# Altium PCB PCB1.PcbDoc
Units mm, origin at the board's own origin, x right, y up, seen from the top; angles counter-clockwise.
Board outline 67.69 x 56.77 mm, 2 copper layers (Top Layer, Bottom Layer); 103 components, 81 nets, 365 pads, 467 vias.
Unrouted connection lines stored in the file: 20.
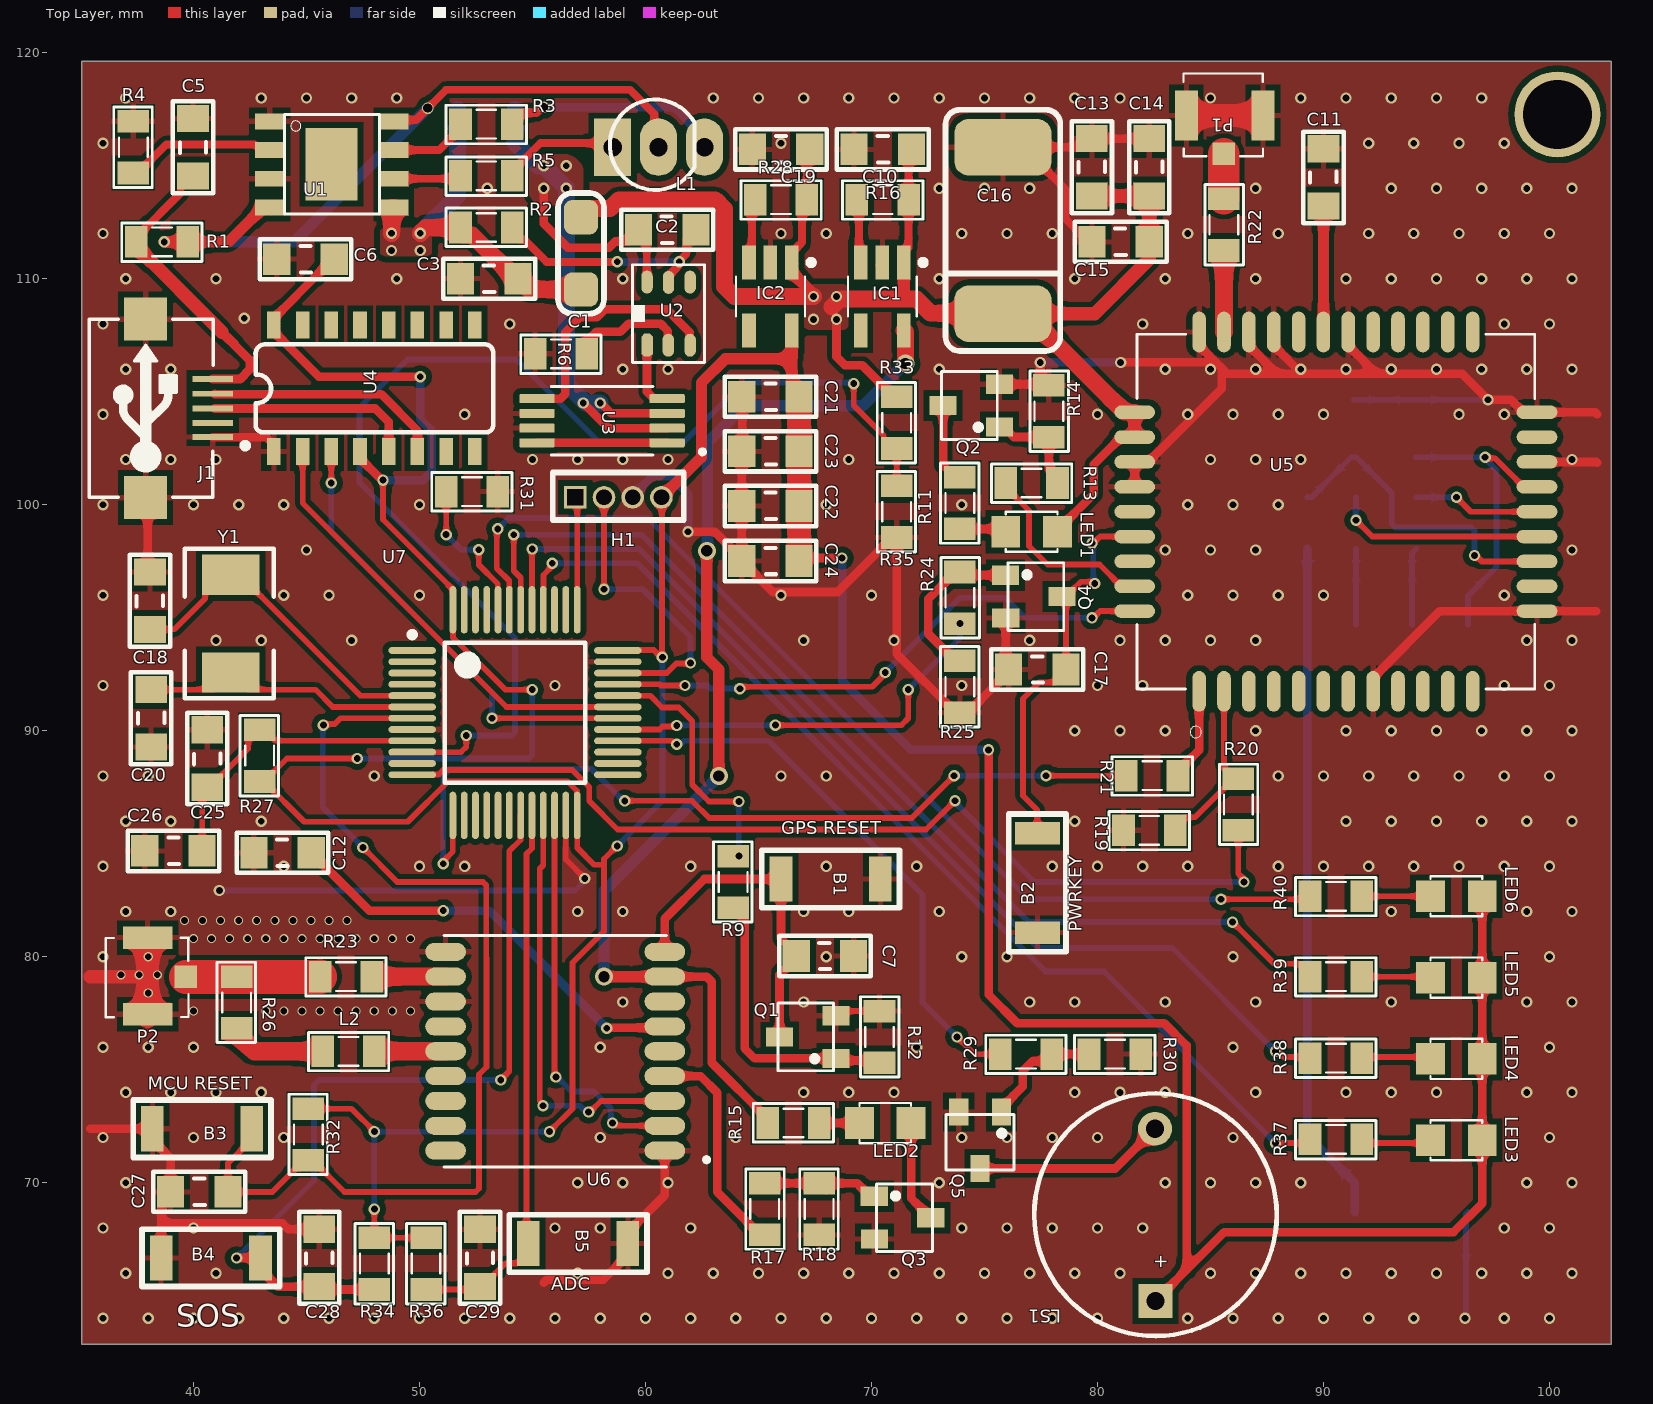
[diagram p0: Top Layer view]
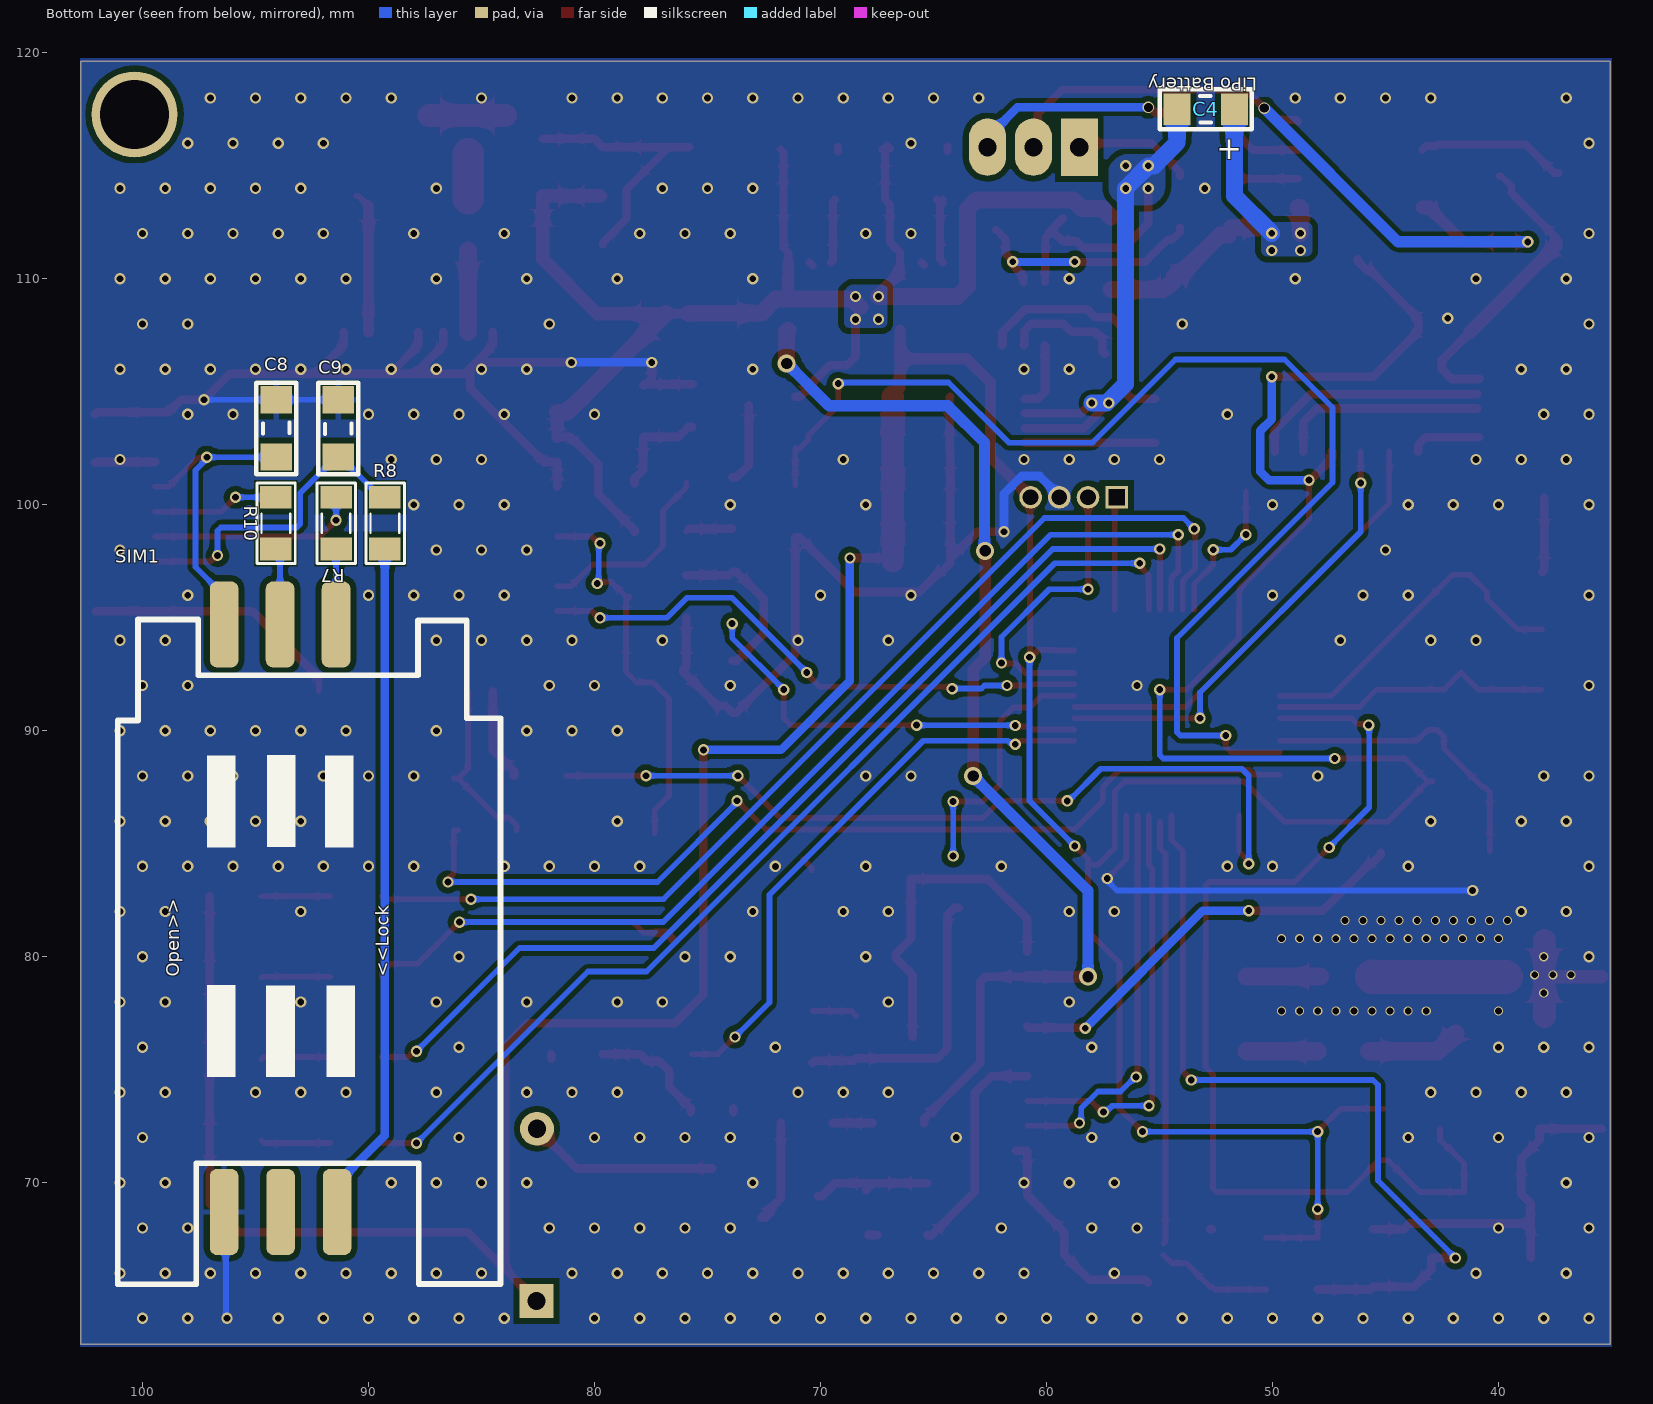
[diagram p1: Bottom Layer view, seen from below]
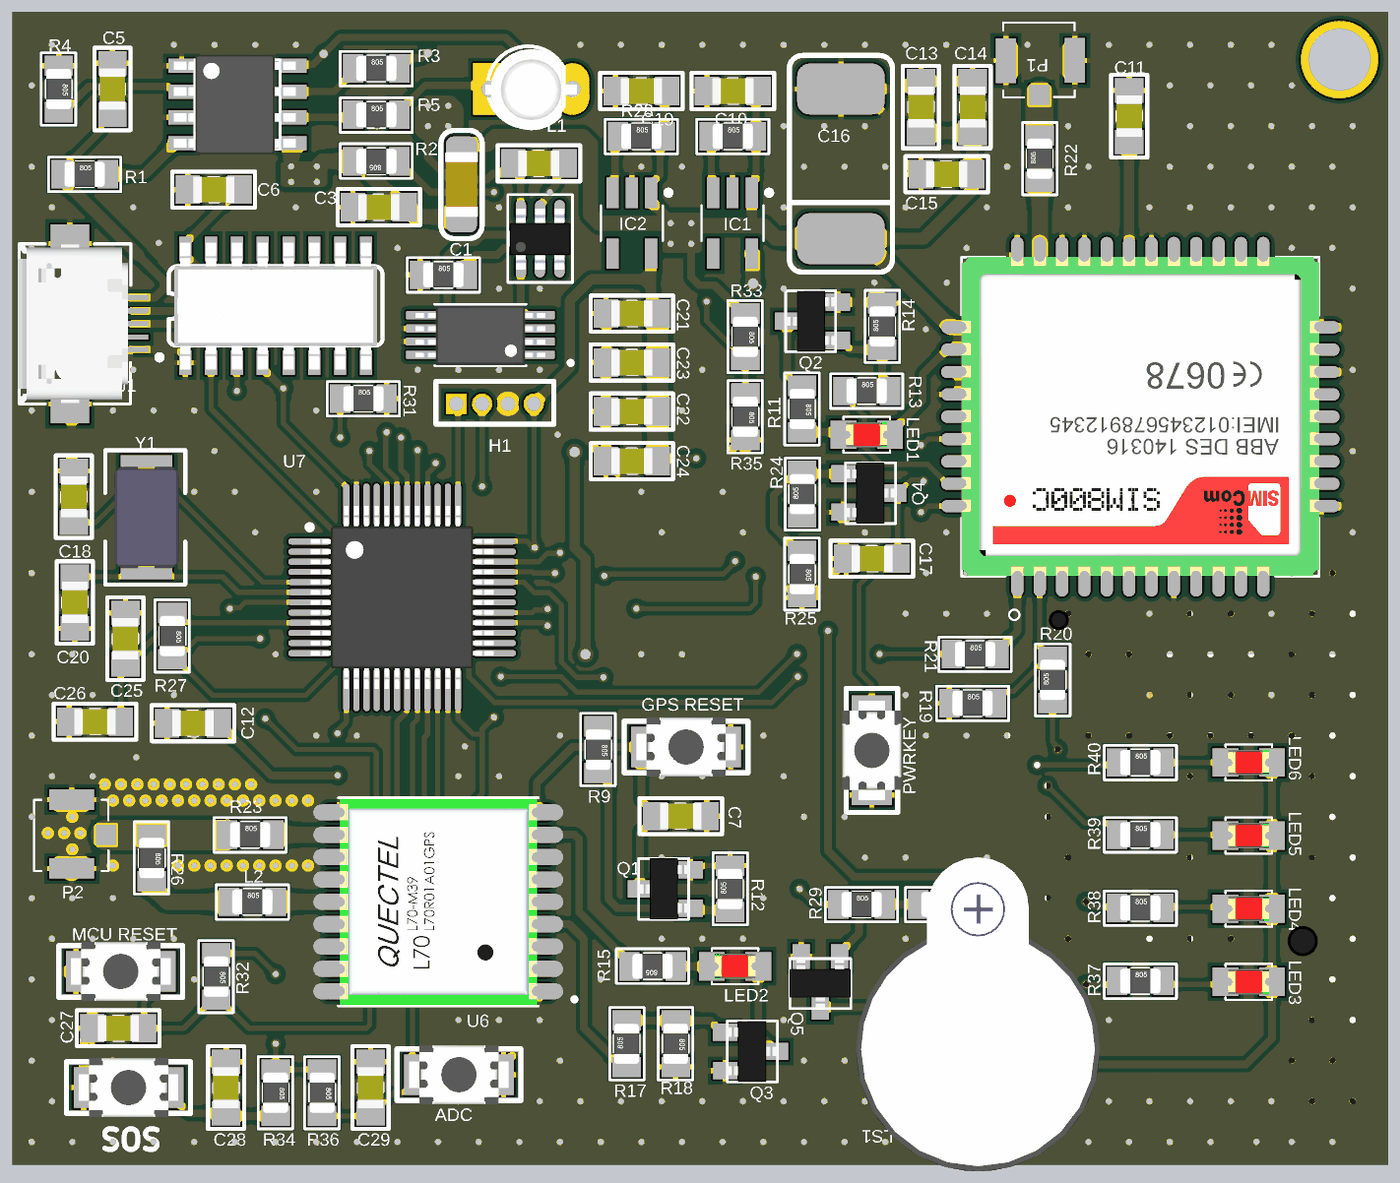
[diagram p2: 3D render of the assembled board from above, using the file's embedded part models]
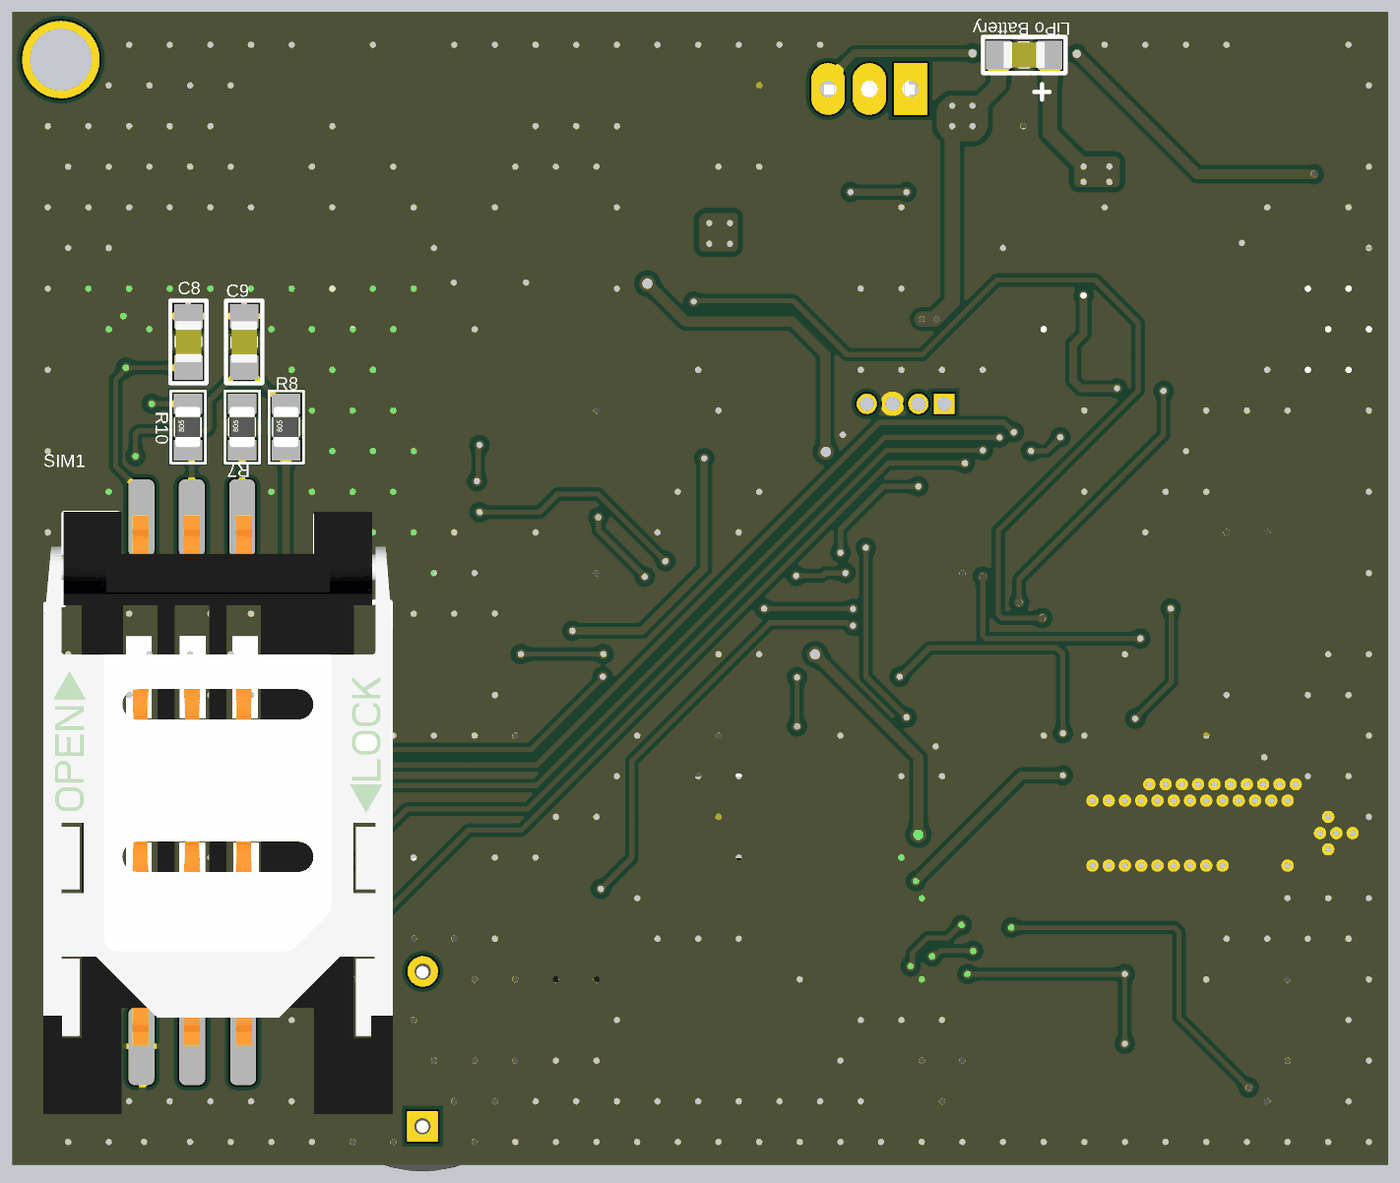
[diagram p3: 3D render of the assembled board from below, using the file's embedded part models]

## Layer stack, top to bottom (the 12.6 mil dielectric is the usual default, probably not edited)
Top Solder: solder mask 0.0102, Solder Resist, Dk 3.5
Top Layer: signal copper 0.0356
Dielectric 1: dielectric 0.32, FR-4, Dk 4.8
Bottom Layer: signal copper 0.0356
Bottom Solder: solder mask 0.0102, Solder Resist, Dk 3.5

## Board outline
35.052,62.865 35.052,119.634 102.743,119.634 102.743,62.865

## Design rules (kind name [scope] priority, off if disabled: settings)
Clearance [All] p1: gap=0.254 ignorepadtopadclearanceinfootprint=TRUE except(0.2: Arc-Arc Arc-Track Arc-SMDPad Arc-THPad Arc-Via Arc-Fill Arc-Poly Arc-Region Arc-Text Arc-Hole Track-Track Track-SMDPad Track-THPad Track-Via Track-Fill Track-Poly Track-Region Track-Text Track-Hole SMDPad-SMDPad)
DiffPairsRouting [All] p1: maxlimit=0.254 minlimit=0.254 mostfreqgap=0.254 toplayer_minwidth=0.381 toplayer_maxwidth=0.381 toplayer_prefwidth=0.381 bottomlayer_minwidth=0.381 bottomlayer_maxwidth=0.381 bottomlayer_prefwidth=0.381 maxuncoupledlength=12.7
HoleSize [All] p1: absolutevalues=TRUE maxlimit=2.54 minlimit=0.5 maxpercent=80.000 minpercent=20.000
MinimumSolderMaskSliver [All] p1: minsoldermaskwidth=0
PlaneConnect [All] p1: planeconnectstyle=Relief reliefexpansion=0.508 reliefentries=4 reliefconductorwidth=0.508 reliefairgap=0.254
PolygonConnect [All] p1: thpad.connectstyle=Direct thpad.reliefconductorwidth=0.508 thpad.reliefentries=4 thpad.polygonreliefangle="90 Angle" thpad.airgapwidth=0.254 smdpad.connectstyle=Relief smdpad.reliefconductorwidth=0.254 smdpad.reliefentries=4 smdpad.polygonreliefangle="90 Angle" smdpad.airgapwidth=0.254 via.connectstyle=Direct via.reliefconductorwidth=0.254 via.reliefentries=4 via.polygonreliefangle="90 Angle" via.airgapwidth=0.254
RoutingVias [All] p1: holewidth=0.3 width=0.5 viastyle="Through Hole" minholewidth=0.1 minwidth=0.1 maxholewidth=0.75 maxwidth=1
SilkToSilkClearance [All] p1: silktosilkclearance=0
SilkToSolderMaskClearance SilkscreenOverComponentPads [IsPad] p1: minsilkscreentomaskgap=0 clearancetoexposedcopper=TRUE
SolderMaskExpansion [All] p1: expansion=0.102
UnRoutedNet [All] p1: checkbadconnections=TRUE
Width [All] p1: maxlimit=3 minlimit=0.127 preferedwidth=0.2
23 further rules are at their usual default settings.

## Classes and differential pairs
component class Designator: B3 B4 B5 C18 C19 C20 C21 C22 C23 C24 C25 C26 C27 C28 C29 H1 IC2 LED3 LED4 LED5 LED6 LS1 Q5 R27 R28 R29 R30 R31 R32 R33 R34 R35 R36 R37 R38 R39 R40 U7 Y1
differential pair D: +D_P -D_N

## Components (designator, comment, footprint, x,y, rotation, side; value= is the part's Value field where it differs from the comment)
B1 "Button 3x4x2.5" "Button 3x4x2.5" 68.199,83.439 r180 top
B2 "Button 3x4x2.5" "Button 3x4x2.5" 77.343,83.271 r90 top
B3 "Button 3x4x2.5" "Button 3x4x2.5" 40.386,72.39 r0 top
B4 "Button 3x4x2.5" "Button 3x4x2.5" 40.767,66.675 r0 top
B5 "Button 3x4x2.5" "Button 3x4x2.5" 57.023,67.31 r180 top
C1 "Pad Switch ON/OFF" CAP_3216 57.15,111.125 r90 top value=33p
C2 "100nF" CAP_0805 60.96,112.141 r180 top value=33p
C3 "10uF" CAP_0805 53.086,109.982 r180 top value=33p
C4 "LiPo Battery" CAP_0805 52.959,117.475 r0 bottom value=33p
C5 "100nF" CAP_0805 40.005,115.824 r270 top value=33p
C6 "100nF" CAP_0805 44.958,110.896 r0 top value=33p
C7 "100nF" CAP_0805 67.945,80.01 r180 top value=33p
C8 "100nF" CAP_0805 94.107,103.378 r90 bottom value=33p
C9 "22pF" CAP_0805 91.313,103.378 r270 bottom value=33p
C10 "1uF" CAP_0805 70.5,115.75 r0 top value=33p
C11 "10nF" CAP_0805 89.976,114.485 r90 top value=33p
C12 "10nF" CAP_0805 43.942,84.582 r180 top value=33p
C13 "1uF" CAP_0805 79.731,114.935 r90 top value=33p
C14 "33pF" CAP_0805 82.271,114.935 r90 top value=33p
C15 "10pF" CAP_0805 81.026,111.608 r180 top value=33p
C16 "100uF" CAP_7343 75.819,112.268 r90 top
C17 "100nF" CAP_0805 77.343,92.735 r0 top value=33p
C18 "22pF" CAP_0805 38.1,95.758 r270 top value=33p
C19 "1uF" CAP_0805 66,115.75 r0 top value=33p
C20 "22pF" CAP_0805 38.1,90.551 r90 top value=33p
C21 "100nF" CAP_0805 65.532,104.8 r0 top value=33p
C22 "100nF" CAP_0805 65.532,99.974 r0 top value=33p
C23 "100nF" CAP_0805 65.532,102.387 r0 top value=33p
C24 "4.7uF" CAP_0805 65.532,97.536 r0 top value=33p
C25 "1uF" CAP_0805 40.64,88.773 r270 top value=33p
C26 "10nF" CAP_0805 39.116,84.709 r0 top value=33p
C27 "100nF" CAP_0805 40.259,69.621 r0 top value=33p
C28 "100nF" CAP_0805 45.593,66.675 r270 top value=33p
C29 "100nF" CAP_0805 52.705,66.675 r270 top value=33p
H1 "Header 1.27mm" "Header 1.27mm" 56.896,100.33 r0 top
IC1 "RT9013" SOT23-5 70.485,109.22 r270 top
IC2 "RT9013" SOT23-5 65.532,109.22 r270 top
J1 "USB-5" USB-M1 40.855,104.264 r90 top
L1 "LED 3mm" "LED-3MM 2 MAU" 60.579,115.824 r0 top
L2 "47nH" RES-SMD-0805 46.863,75.819 r0 top
LED1 "LED" LED-0805-Red 78.232,98.806 r180 top value="LED 3 ly Single Colour"
LED2 "LED" LED-0805-Red 69.469,72.644 r0 top value="LED 3 ly Single Colour"
LED3 "LED RED" LED-0805-Red 97.028,71.882 r180 top value="LED 3 ly Single Colour"
LED4 "LED YELLOW" LED-0805-Red 97.028,75.48 r180 top value="LED 3 ly Single Colour"
LED5 "LED GREEN" LED-0805-Red 97.028,79.079 r180 top value="LED 3 ly Single Colour"
LED6 "LED RED" LED-0805-Red 97.028,82.677 r180 top value="LED 3 ly Single Colour"
LS1 "Speaker" SPEAKER 82.563,64.77 r90 top
P1 "Antenna" IPXS 85.598,115.951 r270 top
P2 "Antenna" IPXS 39.25,79.119 r0 top
Q1 "C1815" SOT23D 67.183,76.454 r90 top
Q2 "C1815" SOT23D 74.422,104.394 r90 top
Q3 "C1815" SOT23D 71.374,68.453 r270 top
Q4 "C1815" SOT23D 77.191,95.936 r270 top
Q5 "C1815" SOT23D 74.803,71.882 r180 top
R1 "0.4R" RES-SMD-0805 38.608,111.633 r0 top
R2 "100R" RES-SMD-0805 52.959,112.268 r180 top
R3 "1k" RES-SMD-0805 52.959,116.84 r0 top
R4 "1.2k" RES-SMD-0805 37.338,115.824 r270 top
R5 "1k" RES-SMD-0805 52.959,114.554 r0 top
R6 "1k" RES-SMD-0805 56.261,106.68 r0 top
R7 "51R" RES-SMD-0805 91.44,99.187 r90 bottom
R8 "51R" RES-SMD-0805 89.281,99.187 r90 bottom
R9 "4.7k" RES-SMD-0805 63.881,83.312 r270 top
R10 "51R" RES-SMD-0805 94.107,99.187 r90 bottom
R11 "1k" RES-SMD-0805 73.914,100.076 r270 top
R12 "47k" RES-SMD-0805 70.358,76.454 r90 top
R13 "4.7k" RES-SMD-0805 77.089,100.965 r0 top
R14 "47k" RES-SMD-0805 77.851,104.14 r90 top
R15 "1k" RES-SMD-0805 66.548,72.644 r180 top
R16 "10k" RES-SMD-0805 70.5,113.5 r0 top
R17 "4.7k" RES-SMD-0805 65.278,68.834 r90 top
R18 "47k" RES-SMD-0805 67.691,68.834 r270 top
R19 "5.6k" RES-SMD-0805 82.296,85.598 r0 top
R20 "1k" RES-SMD-0805 86.233,86.741 r90 top
R21 "1k" RES-SMD-0805 82.423,88.011 r0 top
R22 "0R" RES-SMD-0805 85.598,112.395 r90 top
R23 "0R" RES-SMD-0805 46.75,79.121 r0 top
R24 "4.7k" RES-SMD-0805 73.914,95.885 r90 top
R25 "47k" RES-SMD-0805 73.914,91.948 r270 top
R26 "10R" RES-SMD-0805 41.91,77.978 r270 top
R27 "0R" RES-SMD-0805 42.926,88.9 r270 top
R28 "10k" RES-SMD-0805 66,113.5 r0 top
R29 "4.7k" RES-SMD-0805 76.835,75.692 r0 top
R30 "47k" RES-SMD-0805 80.772,75.692 r0 top
R31 "100k" RES-SMD-0805 52.324,100.584 r0 top
R32 "10k" RES-SMD-0805 45.085,72.136 r270 top
R33 "10k" RES-SMD-0805 71.12,103.632 r270 top
R34 "10k" RES-SMD-0805 48.006,66.421 r270 top
R35 "22k" RES-SMD-0805 71.12,99.695 r270 top
R36 "10k" RES-SMD-0805 50.292,66.421 r270 top
R37 "1k" RES-SMD-0805 90.551,71.92 r0 top
R38 "1k" RES-SMD-0805 90.551,75.518 r0 top
R39 "1k" RES-SMD-0805 90.551,79.121 r0 top
R40 "1k" RES-SMD-0805 90.551,82.677 r0 top
SIM1 "SIM SOCKET 6P" "SIM SOCKET 6P" 104.521,67.056 r90 bottom
U1 "TP4056" TP4056 46.126,115.062 r0 top
U2 "DW01A" SOT23-6 60.894,108.57 r90 top
U3 "FS8205A" FS8205A 58.08,103.774 r180 top
U4 "CH340C" SO016 48.006,105.156 r0 top
U5 "SIM800C" LCC110P1570X1760X250-42N 90.551,99.695 r90 top
U6 "L70-RL" XCVR_L70-RL 56.007,75.819 r180 top
U7 "STM32" "LQFP 48" 54.229,90.805 r0 top
Y1 "8Mhz" "Thach Anh 2 chan SMD5032" 41.656,94.742 r90 top value=4Mhz

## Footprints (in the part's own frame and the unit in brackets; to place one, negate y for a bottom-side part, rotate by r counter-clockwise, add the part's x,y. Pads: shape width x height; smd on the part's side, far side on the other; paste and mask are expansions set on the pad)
"Button 3x4x2.5" [mm]
  rect 1x2 smd: 15(-2.2,0) 19(2.2,0)
  silkscreen extent -3.05,-1.27 3.05,1.27, body extent -2.45,-1.45 2.45,1.45, height 2
CAP_0805 [mm]
  rect 1.2x1.4 smd: 1(-1.27,-0.025) 2(1.27,-0.025)
  silkscreen extent -2.03,-0.91 2.03,0.86, body extent -1.01,-0.66 1.01,0.61, height 0.61
CAP_3216 [mil]
  rrect50% 60x60 smd: 1(-62.99,0) s(62.99,0)
  silkscreen extent -105,-40 105,40, body extent -63,-31 63,31, height 39
CAP_7343 [mm] "Capacitor Tantalum 7343"
  rrect50% 2.5x4.3 smd: 1(-3.81,0) 2(3.556,0)
  silkscreen extent -5.46,-2.54 5.21,2.54, body extent -3.81,-2.29 3.56,2.29, height 3
FS8205A [mm]
  rrect25% 1.56x0.4 smd: 1(-2.88,1.031) 2(-2.88,0.381) 3(-2.88,-0.269) 4(-2.88,-0.919) 5(2.88,-0.919) 6(2.88,-0.269) 7(2.88,0.381) 8(2.88,1.031)
  silkscreen extent -4.54,-1.46 2.25,1.57, body extent -3.2,-1.4 3.2,1.53, height 1.2
"Header 1.27mm" [mm]
  rect 1x1 hole 0.7 square: 1(0,0)
  round 1 hole 0.7: 2(1.27,0) 3(2.54,0) 4(3.81,0)
  silkscreen extent -1,-1 4.8,1.1
IPXS [mm] "SOT 23 _ 1-3-2"
  rect 1x1 smd: 1(0.415,-0.01)
  rect 2.2x1 smd: 2(-1.273,-1.658) 3(-1.278,1.73)
  silkscreen extent -3.13,-1.79 0.53,1.73, body extent -2.83,-1.49 0.31,1.56, height 1.55
LCC110P1570X1760X250-42N [mm]
  oval 1.8x0.6 smd: 1(-7.95,6.05) 2(-7.95,4.95) 3(-7.95,3.85) 4(-7.95,2.75) 5(-7.95,1.65) 6(-7.95,0.55) 7(-7.95,-0.55) 8(-7.95,-1.65) 9(-7.95,-2.75) 10(-7.95,-3.85) 11(-7.95,-4.95) 12(-7.95,-6.05) 22(7.95,-6.05) 23(7.95,-4.95) 24(7.95,-3.85) 25(7.95,-2.75) 26(7.95,-1.65) 27(7.95,-0.55) 28(7.95,0.55) 29(7.95,1.65) 30(7.95,2.75) 31(7.95,3.85) 32(7.95,4.95) 33(7.95,6.05)
  oval 0.6x1.8 smd: 13(-4.4,-8.9) 14(-3.3,-8.9) 15(-2.2,-8.9) 16(-1.1,-8.9) 17(0,-8.9) 18(1.1,-8.9) 19(2.2,-8.9) 20(3.3,-8.9) 21(4.4,-8.9) 34(4.4,8.9) 35(3.3,8.9) 36(2.2,8.9) 37(1.1,8.9) 38(0,8.9) 39(-1.1,8.9) 40(-2.2,8.9) 41(-3.3,8.9) 42(-4.4,8.9)
  silkscreen extent -10,-8.8 7.85,8.8, body extent -7.83,-8.8 7.87,8.8, height 2.31
"LED-3MM 2 MAU" [mil] "LED 3 PIN, 3ly Two colour"
  rect 65x100 hole 32: 1(-80,0)
  oval 65x100 hole 32: 2(0,0) 3(80,0)
  silkscreen extent -85,-75 63,83, body extent -89,-80 89,77, height 293
LED-0805-Red [mil]
  rect 50x55 smd: 1(0,0) 2(90,0)
  silkscreen extent 0,-35 90,35, body extent 5,-25 85,25, height 43
"LQFP 48" [mm] "LQFP, 48-Leads, Body 7,00x7,00mm, Pitch 0,50mm, IPC Medium Density"
  oval 2.1x0.3 smd: 1(-4.55,2.75) 2(-4.55,2.25) 3(-4.55,1.75) 4(-4.55,1.25) 5(-4.55,0.75) 6(-4.55,0.25) 7(-4.55,-0.25) 8(-4.55,-0.75) 9(-4.55,-1.25) 10(-4.55,-1.75) 11(-4.55,-2.25) 12(-4.55,-2.75) 25(4.55,-2.75) 26(4.55,-2.25) 27(4.55,-1.75) 28(4.55,-1.25) 29(4.55,-0.75) 30(4.55,-0.25) 31(4.55,0.25) 32(4.55,0.75) 33(4.55,1.25) 34(4.55,1.75) 35(4.55,2.25) 36(4.55,2.75)
  oval 0.3x2.1 smd: 13(-2.75,-4.55) 14(-2.25,-4.55) 15(-1.75,-4.55) 16(-1.25,-4.55) 17(-0.75,-4.55) 18(-0.25,-4.55) 19(0.25,-4.55) 20(0.75,-4.55) 21(1.25,-4.55) 22(1.75,-4.55) 23(2.25,-4.55) 24(2.75,-4.55) 37(2.75,4.55) 38(2.25,4.55) 39(1.75,4.55) 40(1.25,4.55) 41(0.75,4.55) 42(0.25,4.55) 43(-0.25,4.55) 44(-0.75,4.55) 45(-1.25,4.55) 46(-1.75,4.55) 47(-2.25,4.55) 48(-2.75,4.55)
  silkscreen extent -4.67,-3.1 3.1,3.57, body extent -4.5,-4.5 4.5,4.5, height 1.6
RES-SMD-0805 [mil]
  rect 39.37x55 smd: 1(-45,0) 2(45,0)
  silkscreen extent -70,-34 70,33, body extent -39,-25 39,25, height 31
"SIM SOCKET 6P" [mil]
  rrect50% 150x50 smd: 1(65,-320) 2(1088.62,-320) 3(65,-418.43) 4(1088.62,-417.5) 5(65,-516.85) 6(1088.62,-515)
  silkscreen extent -61,-802 1097,-135, body extent -66,-807 1101,-130, height 103
SO016 [mm]
  rect 0.6x1.2 smd: 1(-4.445,-2.8) 2(-3.175,-2.8) 3(-1.905,-2.8) 4(-0.635,-2.8) 5(0.635,-2.8) 6(1.905,-2.8) 7(3.175,-2.8) 8(4.445,-2.8) 9(4.445,2.8) 10(3.175,2.8) 11(1.905,2.8) 12(0.635,2.8) 13(-0.635,2.8) 14(-1.905,2.8) 15(-3.175,2.8) 16(-4.445,2.8)
  silkscreen extent -5.84,-2.67 5.26,1.95, body extent -4.99,-3.13 4.99,3.1, height 1.58
SOT23-5 [mm] "SOT23, 5-Leads, Body 3.0x3.0mm (max), Pitch 0.95mm, IPC Medium Density"
  rect 1.5x0.6 smd: 1(-1.5,0.95) 2(-1.5,0) 3(-1.5,-0.95) 4(1.5,-0.95) 5(1.5,0.95)
  silkscreen extent -1.62,-1.52 0.87,1.93, body extent -1.75,-1.52 1.75,1.53, height 1.45
SOT23-6 [mil]
  oct 40x20 smd: 1(-59.41,32.4)
  oval 40x20 smd: 2(-59.41,-4.6) 3(-59.41,-42.6) 4(50.59,-42.6) 5(50,-5) 6(50.59,32.4)
  silkscreen extent -89,-68 81,57, body extent -64,-64 54,54, height 51
SOT23D [mm] "SOT 23C - 1-3-2 - BCE"
  rect 0.85x1.2 smd: 1(-0.95,-1.25) 2(0.94,-1.245) 3(0,1.25)
  silkscreen extent -1.5,-1.14 1.5,1.32, body extent -1.5,-1.17 1.5,1.33, height 1.06
SPEAKER [mm]
  rect 1.5x1.5 hole 0.8: 1(0,0)
  round 1.5 hole 0.8: 2(7.62,0.013)
  silkscreen extent -1.55,-5.38 9.18,5.36, body extent -2.22,-6 13.24,6, height 4.5
"Thach Anh 2 chan SMD5032" [mil] "DO-214-AA/SMB; 2 C-Bend Leads; Body 5.3 x 3.6 mm, inc. leads (LxW)"
  rect 70x100 smd: 1(-85,0) 2(85,0)
  silkscreen extent -130,-75 130,80, body extent -98,-63 98,63, height 51
TP4056 [mm]
  rect 1.3x0.7 smd: 1(-2.75,1.905) 2(-2.75,0.635) 3(-2.75,-0.635) 4(-2.75,-1.905) 5(2.75,-1.905) 6(2.75,-0.635) 7(2.75,0.635) 8(2.75,1.905)
  rect 2.3x3.2 smd: GND(-0.025,0)
  silkscreen extent -2.1,-2.2 2.1,2.2, body extent -3.13,-2.45 2.87,2.45, height 1.75
USB-M1 [mil]
  rect 10x70 smd: 1(51.18,0) 2(25.59,0) 3(0,0) 4(-25.59,0) 5(-50,0)
  rect 74.8x74.8 smd: 5(-155.51,116.84) 5(155.51,116.84)
  silkscreen extent -155,-1 155,215, body extent -157,5 158,218, height 107
XCVR_L70-RL [mm]
  oval 1.8x0.8 smd paste-2: 1(-4.85,4.4) 2(-4.85,3.3) 3(-4.85,2.2) 4(-4.85,1.1) 5(-4.85,0) 6(-4.85,-1.1) 7(-4.85,-2.2) 8(-4.85,-3.3) 9(-4.85,-4.4) 10(4.85,-4.4) 11(4.85,-3.3) 12(4.85,-2.2) 13(4.85,-1.1) 14(4.85,0) 15(4.85,1.1) 16(4.85,2.2) 17(4.85,3.3) 18(4.85,4.4)
  silkscreen extent -6.8,-5.13 4.92,5.13, body extent -4.85,-5.05 4.85,5.05, height 2.52

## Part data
C1 C2 C3 C4 C5 C6 C7 C8 C9 C10 C11 C12 C13 C14 C15 C17 C18 C19 C20 C21 C22 C23 C24 C25 C26 C27 C28 C29: library part CapSMD, "Capacitor"
C16: library part CAP_TAN_SMD, "Polazied Tantalum Capacitor"
IC1 IC2: "RT9013-33GB IC REG LINEAR 3.3V 500mA SOT23-5"
J1: Manufacturer=FCI, Manufacturer Part Number=10118193-0001LF, Supplier Part Number 1=609-4616-1-ND
L1: library part "LED 3m 2 mau Anot chung", "C?m"
L2 R1 R2 R3 R4 R5 R6 R7 R8 R9 R10 R11 R12 R13 R14 R15 R16 R17 R18 R19 R20 R21 R22 R23 R24 R25 R26 R27 R28 R29 R30 R31 R32 R33 R34 R35 R36 R37 R38 R39 R40: library part "Resistor - SMD", "Resistor", Manufacturer="Generic Components"
LED1 LED2: "LED Single colour Green and Red"
LED3 LED4 LED5 LED6: library part LED, "LED Single colour Green and Red"
LS1: "Còi chíp 3V"
P1 P2: library part IPXSx66, "Antenna GSM GPS"
Q1 Q2 Q3 Q4 Q5: library part 2SC1815, "NPN 600mW, ECB"
U1: "Complete single cell Li-Ion battery with a constant current / constant voltage linear charger"
U2: "One Cell Lithium-ion/Polymer Battery Protection IC"
U4: "USB to serial chip CH340", Package=Package
U5: "Module: GSM/Bluetooth; GPRS; 2G; 1800MHz, 900MHz; 85.6kbps; SMD", Package=None
U6: "L70-RL, a low cost ROM-based GPS module, brings the high performance of MTK positioning engine to industrial applications with its compact profile, ultra low power consumption and fast positioning capability", Package=None
U7: library part STM32F103C8T6, "STM32 ARM-based 32-bit MCU with 64 Kbytes Flash, 64-pin LQFP, Industrial Temperature"
Y1: library part "Thach Anh 2 chan SMD 5032", "Crystal For all Crystal 2pin."

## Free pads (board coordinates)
  round 3.81 hole 3.048: 0(100.355,117.272)

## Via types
v1: diameter 0.5, hole 0.3, Top Layer to Bottom Layer, tented both sides, 423 vias
v2: diameter 0.4, hole 0.3, Top Layer to Bottom Layer, 38 vias
v3: diameter 0.8, hole 0.5, Top Layer to Bottom Layer, tented both sides, 4 vias
v4: diameter 0.5, hole 0.4, Top Layer to Bottom Layer, tented both sides, 2 vias

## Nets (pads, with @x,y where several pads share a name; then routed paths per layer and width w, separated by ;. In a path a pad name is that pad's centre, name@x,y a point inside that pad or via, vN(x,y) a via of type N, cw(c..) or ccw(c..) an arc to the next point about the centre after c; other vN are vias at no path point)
3V3: C6.2 C21.2 C22.2 C23.2 C24.2 H1.4 IC2.5 LED3.1 LED4.1 LED5.1 LED6.1 LS1.1 R27.2 R32.1 R34.1 R36.1 U4.4 U4.16 U7.24 U7.36 U7.48 | length 214.1
  Top Layer w0.254: R27.2 R27.2@43.124,87.757 ; R32.1 46.99,73.279 v1(48.006,72.263) ; v1(47.244,88.773) 44.14,88.773 R27.2@43.124,87.757 ; v1(48.006,68.834) R34.1 R36.1 ; v1(48.387,101.092) 48.387,99.347 51.479,96.255 U7.48 51.488,95.346 51.488,94.13 53.796,91.821 v1(54.991,91.821) ; v1(55.753,72.263) 56.769,73.279 56.769,79.733 58.166,81.13 58.166,84.328 58.736,84.898 v1(58.749,84.898) ; 58.122,84.074 57.726,84.074 56.979,84.821 U7.24 56.97,86.264 56.97,87.338 56.552,87.757 51.257,87.757 49.479,85.979 44.903,85.979 R27.2@43.124,87.757 ; U7.36 59.68,93.555 59.694,93.57 60.364,93.57 60.683,93.25 v1(60.75,93.25) 60.728,93.272 60.728,100.308 H1.4
  Top Layer w0.381: C6.2 46.228,110.771 45.818,110.361 45.666,110.361 43.561,108.256 U4.16 43.561,107.656 45.553,105.664 v1(50.038,105.664) ; U4.4 47.371,102.056 48.311,101.116 48.363,101.116 v1(48.387,101.092) ; C24.2 66.936,97.644 v1(68.7,97.644) ; v1(75.184,89.154) 75.184,78.328 76.453,77.059 82.961,77.059 83.947,76.073 83.947,66.154 ; LS1.1 83.947,66.154 ; LED6.1 LED5.1 LED4.1 LED3.1 97.028,69.088 95.758,67.818 85.611,67.818 83.947,66.154
  Top Layer w0.5: H1.4 62.484,102.108 62.484,105.41 63.532,106.458 66.482,106.458 ; IC2.5 66.482,106.458 ; C21.2@66.802,104.875 66.482,105.195 66.482,106.458
  Top Layer w0.75: C21.2 C21.2@66.802,104.875
  Top Layer w1: C24.2 C22.2 C23.2 C21.2
  Bottom Layer w0.254: v1(47.244,88.773) 54.842,88.773 54.991,88.922 v1(54.991,91.821) ; v1(48.006,68.834) v1(48.006,72.263) v1(55.753,72.263) ; v1(58.749,84.898) 60.75,86.9 v1(60.75,93.25)
  Bottom Layer w0.381: v1(48.387,101.092) 50.165,101.092 50.546,101.473 50.546,103.271 50.038,103.779 v1(50.038,105.664) ; v1(68.7,97.644) 68.707,97.637 68.707,92.202 71.755,89.154 v1(75.184,89.154)
3V3GPS: IC1.5 R15.2 U6.8 | length 49.8
  Top Layer w0.381: U6.8 62.713,79.119 62.937,78.896 62.937,75.311 65.405,72.842 R15.2
  Top Layer w0.5: v3@58.168,79.119 U6.8 ; v3(62.717,97.961) 62.717,93.247 63.25,92.714 v3(63.25,88)
  Top Layer w0.75: v3(58.166,79.121) v3@58.168,79.119 ; IC1.5 71.5,107.655 v3(71.5,106.25)
  Bottom Layer w0.5: v3(58.166,79.121) 58.166,82.916 v3(63.25,88) ; v3(62.717,97.961) 62.75,97.995 62.75,102.755 64.378,104.383 69.621,104.383 71.488,106.25 v3(71.5,106.25)
+5: C5.2 J1.1 R1.1 | length 13.6
  Top Layer w0.3: R1.1 R1.1@37.465,111.831 ; 39.43,113.796 39.43,114.104 39.88,114.554 C5.2
  Top Layer w0.35: R1.1@37.465,111.831 39.43,113.796
  Top Layer w0.4: J1.1 42.064,105.564 42.5,106 42.5,106.399 41.254,107.645
  Top Layer w0.6: R1.1 37.465,111.435 41.254,107.645
BOOT0: R31.1 U7.44 | length 6.6
  Top Layer w0.254: v1(51.181,98.679) R31.1 ; v1(52.621,98.009) 52.621,97.347 53.47,96.498 53.47,95.364 U7.44
  Bottom Layer w0.254: v1(51.181,98.679) 51.851,98.009 v1(52.621,98.009)
BUT_ADC: B5.19 C29.2 R36.2 U7.20 | length 24
  Top Layer w0.254: R36.2 52.553,65.278 C29.2 52.78,65.405 53.812,66.437 54.45,66.437 B5.19@54.823,66.81 ; B5.19 54.737,67.396 54.737,84.555 54.979,84.797 U7.20@54.979,85.979
BUT_SOS: B4.19 C28.2 R34.2 U7.19 | length 36.5
  Top Layer w0.254: v1(53.594,74.549) 53.975,74.93 53.975,84.676 54.47,85.172 54.47,86.246 U7.19
  Top Layer w0.381: v1(41.91,66.675) B4.19 42.967,66.175 43.737,65.405 C28.2 45.695,65.278 R34.2
  Bottom Layer w0.254: v1(41.91,66.675) 45.339,70.104 45.339,74.326 45.562,74.549 v1(53.594,74.549)
BUZZER: R29.1 U7.28 | length 25.6
  Top Layer w0.254: U7.28 61.167,89.555 61.314,89.408 v1(61.381,89.408) ; v1(73.787,76.454) 74.549,75.692 R29.1
  Bottom Layer w0.254: v1(61.381,89.408) 61.428,89.455 61.613,89.455 61.713,89.555 65.454,89.555 72.263,82.746 72.263,77.978 v1(73.787,76.454)
D_N: J1.2 U4.6 | length 10.6
  Top Layer w0.381: J1.2@40.941,104.904 40.948,104.896 48.307,104.896 49.911,103.292 U4.6
D_P: J1.3 U4.5 | length 9.3
  Top Layer w0.381: J1.3@40.941,104.254 40.948,104.261 48.044,104.261 48.641,103.664 U4.5
GND: B1.15 B2.15 B3.15 B4.15 B5.15 C3.2 C5.1 C6.1 C7.1 C8.2 C9.1 C10.1 C11.2 C12.2 C13.2 C14.2 C15.2 C16.2 C17.1 C18.1 C19.1 C20.1 C21.1 C22.1 C23.1 C24.1 C25.1 C26.1 C27.1 C28.1 C29.1 H1.3 IC1.2 IC2.2 J1.5 P1.2 P1.3 P2.2 P2.3 Q1.2 Q2.2 Q3.2 Q4.2 Q5.2 R4.1 R6.1 R12.2 R14.2 R18.2 R19.1 R25.2 R30.2 R31.2 R35.2 SIM1.1 U1.1 U1.3 U3.6 U3.7 U4.1 U5.8 U5.13 U5.19 U5.21 U5.27 U5.30 U5.31 U5.33 U5.36 U5.37 U6.1 U6.10 U6.12 U7.8 U7.23 U7.35 U7.47 | length 187.8
  Top Layer w0.25: U5.8 U5.8@92.201,92.345
  Top Layer w0.254: U7.23 56.479,84.307 v1(57.318,83.468) ; Q1.2 68.631,77.597 70.16,77.597 R12.2 ; B1.15@70.399,83.82 70.399,83.939 B1.15@70.772,84.312 ; B2.15 77.843,81.071 B2.15@78.216,81.444 ; 102.063,95.295 102.108,95.25
  Top Layer w0.35: C19.1@64.389,115.663 64.389,115.763 C19.1@64.389,115.863 ; IC2.2@65.425,110.613 IC2.2 ; C10.1@69.23,115.625 C10.1 C10.1@69.23,115.825 ; IC1.2@70.36,110.595 IC1.2 ; C16.2@76.719,115.824 78.584,113.959 78.584,112.651 79.629,111.606 C15.2@79.629,111.506
  Top Layer w0.381: 35.433,72.39 B3.15 38.186,71.89 38.989,71.087 C27.1 38.989,69.496 38.567,69.074 38.567,68.199 ; J1.5@37.973,100.304 37.973,97.13 C18.1 ; B4.15 38.567,68.199 ; J1.5@40.855,102.994 43.223,102.994 43.561,102.656 U4.1 ; C28.1 44.196,67.945 43.942,68.199 38.567,68.199 ; C29.1 C29.1@52.78,67.945 ; 55.499,65.581 55.626,65.708 58.121,65.708 59.223,66.81 B5.15 59.223,67.81 60.857,69.444 U6.1 U6.1@61.357,71.419 ; v1(61.886,98.806) 63.067,98.806 C24.1@64.262,97.611 ; C21.1 64.29,104.747 64.29,102.39 C23.1 C22.1 C24.1@64.262,97.611 ; R18.2@67.493,67.691 R18.2 R18.2@67.889,67.691 ; Q5.2 Q5.2@73.863,73.302 ; Q2.2 R14.2@77.729,105.334 ; C16.2 76.719,115.824 79.629,115.824 80.01,116.205 C14.2 ; Q4.2 75.946,92.837 C17.1 76.073,92.61 74.578,91.115 74.224,91.115 74.013,90.904 R25.2 73.716,90.805 71.12,93.401 R35.2 70.922,98.552 68.508,96.139 65.634,96.139 64.772,97.001 64.672,97.001 64.262,97.411 C24.1 C24.1@64.262,97.611 ; B2.15@76.533,80.761 76.843,81.071 B2.15 ; v1(77.47,106.299) 77.47,105.592 R14.2@77.729,105.334 ; R14.2 R14.2@77.838,105.296 ; v1(81.026,106.299) 85.247,106.299 ; U5.37 U5.36 82.251,101.895 85.501,105.145 85.501,106.045 ; R30.2@81.915,75.494 R30.2 ; U5.33 84.501,107.045 85.247,106.299 ; U5.31 86.701,107.045 87.955,105.791 ; U5.30 87.801,107.045 v1@89.055,105.791 ; U5.27 91.101,107.045 92.355,105.791 ; U5.8@92.201,92.345 95.151,95.295 U5.13 102.063,95.295 ; U5.19 102.067,101.895 102.108,101.854 ; 102.108,104.013 102.026,104.095 U5.21 98.851,104.095 98.298,104.648 v1(97.282,104.648) 96.139,105.791 92.355,105.791 ; R14.2@77.729,105.334 77.8,105.334 R14.2@77.838,105.296 ; R14.2@77.729,105.334 77.766,105.296 R14.2@77.838,105.296 ; 85.247,106.299 85.501,106.045 ; 85.501,106.045 85.755,105.791 87.955,105.791 ; 87.955,105.791 v1@89.055,105.791 ; v1@89.055,105.791 92.355,105.791
  Top Layer w0.6: 35.433,79.121 37.876,79.121 37.965,79.032 37.968,79.03
  Top Layer w1: 37.965,79.032 P2.3@37.965,80.724 ; P2.2@37.968,77.338 37.968,79.03 ; P1.2 87.328,117.224 P1.3
  Bottom Layer w0.25: C9.1 C8.2 v1(97.282,104.648)
  Bottom Layer w0.254: v1(41.148,82.931) 56.878,82.931 57.318,83.371 v1(57.318,83.468) ; v1(96.266,64.008) 96.315,64.057 96.315,68.629 SIM1.1
  Bottom Layer w0.381: H1.3 59.436,100.396 60.315,101.275 61.097,101.275 61.886,100.486 v1(61.886,98.806) ; v1(77.47,106.299) v1(81.026,106.299)
  other v1: 36,64 38,64 40,64 42,64 44,64 46,64 48,64 50,64 52,64 54,64 56,64 58,64 60,64 62,64 64,64 66,64 68,64 70,64 72,64 74,64 76,64 78,64 80,64 84,64 86,64 88,64 90,64 92,64 94,64 98,64 100,64 37,66 41,66 57,66 61,66 63,66 65,66 67,66 69,66 71,66 73,66 75,66 77,66 79,66 81,66 85,66 87,66 89,66 91,66 93,66 95,66 97,66 99,66 101,66 36,68 40,68 56,68 58,68 62,68 74,68 76,68 78,68 80,68 82,68 98,68 100,68 37,70 57,70 59,70 61,70 73,70 83,70 85,70 87,70 89,70 99,70 101,70 36,72 40,72 44,72 58,72 64,72 74,72 76,72 78,72 80,72 86,72 100,72 37,74 39,74 41,74 43,74 67,74 69,74 71,74 79,74 81,74 83,74 87,74 91,74 93,74 95,74 99,74 101,74 36,76 38,76 40,76 58,76 72,76 86,76 100,76 59,78 67,78 77,78 79,78 83,78 87,78 93,78 99,78 101,78 36,80 68,80 74,80 76,80 86,80 100,80 37,82 39,82 57,82 59,82 67,82 69,82 73,82 93,82 99,82 101,82 36,84 44,84 50,84 52,84 62,84 68,84 72,84 78,84 80,84 82,84 84,84 88,84 90,84 92,84 94,84 96,84 98,84 100,84 37,86 39,86 43,86 79,86 91,86 93,86 95,86 97,86 99,86 101,86 36,88 38,88 48,88 66,88 68,88 88,88 90,88 92,88 94,88 96,88 98,88 100,88 79,90 81,90 83,90 87,90 91,90 93,90 95,90 97,90 99,90 101,90 36,92 56,92 74,92 80,92 82,92 98,92 100,92 41,94 43,94 47,94 67,94 71,94 77,94 81,94 83,94 85,94 87,94 99,94 101,94 36,96 44,96 46,96 50,96 66,96 70,96 84,96 86,96 88,96 90,96 98,96 45,98 83,98 85,98 87,98 101,98 36,100 40,100 42,100 44,100 50,100 68,100 74,100 84,100 86,100 88,100 37,102 39,102 41,102 55,102 57,102 59,102 61,102 69,102 85,102 87,102 89,102 101,102 36,104 38,104 52,104 80,104 84,104 86,104 88,104 90,104 96,104 98,104 37,106 39,106 59,106 61,106 73,106 83,106 85,106 87,106 89,106 91,106 93,106 95,106 97,106 99,106 101,106 36,108 54,108 82,108 98,108 100,108 42.25,108.25 37,110 41,110 49,110 59,110 73,110 79,110 83,110 87,110 91,110 93,110 95,110 97,110 99,110 101,110 36,112 66,112 68,112 74,112 76,112 78,112 84,112 88,112 92,112 94,112 96,112 98,112 100,112 53,114 73,114 75,114 77,114 87,114 93,114 95,114 97,114 99,114 101,114 36,116 66,116 92,116 94,116 96,116 98,116 37,118 43,118 45,118 47,118 49,118 63,118 65,118 67,118 69,118 71,118 73,118 75,118 77,118 79,118 81,118 85,118 89,118 91,118 93,118 95,118 97,118
  other v2: 40,77.6 43.2,77.6 44,77.6 44.8,77.6 45.6,77.6 46.4,77.6 47.2,77.6 48,77.6 48.8,77.6 49.6,77.6 38,78.4 36.8,79.2 37.6,79.2 38.4,79.2 38,80 40,80.8 40.8,80.8 41.6,80.8 42.4,80.8 43.2,80.8 44,80.8 44.8,80.8 45.6,80.8 46.4,80.8 47.2,80.8 48,80.8 48.8,80.8 49.6,80.8 39.6,81.6 40.4,81.6 41.2,81.6 42,81.6 42.8,81.6 43.6,81.6 44.4,81.6 45.2,81.6 46,81.6 46.8,81.6
GPS_RESET: B1.19 C7.2 Q1.3 U6.9 | length 14.9
  Top Layer w0.381: U6.9 60.857,81.685 62.611,83.439 B1.19 65.999,80.811 66.675,80.135 66.675,79.935 65.933,79.193 Q1.3
LIPO_ADC: R33.2 R35.1 U7.10 | length 53.2
  Top Layer w0.254: U7.10 51.844,89.055 52.07,89.281 v1(52.07,89.789) ; v1(69.215,105.362) 69.215,104.394 70.549,103.061 70.549,102.862 70.922,102.489 R33.2 R35.1
  Bottom Layer w0.254: v1(52.07,89.789) 54.08,89.789 54.229,89.938 54.229,94.107 47.349,100.987 47.349,104.305 49.47,106.426 54.296,106.426 57.972,102.75 61.676,102.75 64.336,105.41 69.167,105.41 v1(69.215,105.362)
LIPO_BATTERY: C10.2 C13.1 C14.1 C15.1 C16.1 C19.2 IC1.1 IC2.1 LED1.1 R16.2 R28.2 R33.1 U5.34 U5.35 | length 68.1
  Top Layer w0.35: IC2.1@66.482,110.27 IC2.1 66.482,111.17 66.929,111.617 66.929,113.286 R28.2 67.143,115.598 C19.2 ; C19.2@66.929,115.763 C19.2@67.056,115.89 ; v1@67.408,109.249 v1@67.408,109.344 ; IC1.1 71.435,111.17 71.643,111.378 R16.2 71.643,115.598 C10.2 ; C16.1 C16.1@76.838,108.458
  Top Layer w0.381: v1(68.453,108.204) 68.453,106.547 68.828,106.172 69.596,106.172 70.612,105.156 70.612,105.085 70.922,104.775 R33.1 ; LED1.1 78.232,98.87 79.843,100.48 79.843,101.787 81.051,102.995 U5.35
  Top Layer w0.5: IC2.1@66.482,110.27 v1@67.408,109.344 ; 71.435,109.099 IC1.1
  Top Layer w0.508: U5.35 U5.34
  Top Layer w0.6: C16.1@76.838,108.458 79.883,108.458 82.296,110.871 C15.1 C14.1 C13.1
  Top Layer w0.75: 57.15,112.725 57.533,113.108 58.442,113.108 58.829,113.495 63.091,113.495 63.501,113.085 63.501,109.659 63.94,109.22 v1(67.437,109.22) ; 68.25,108.75 68.599,109.099 71.435,109.099 71.996,109.099 72.62,108.474 75.803,108.474 C16.1 ; C16.1@76.838,108.458 81.201,104.095 U5.34
  other v1: 67.437,108.204 68.453,109.22
LIPO_CHARGER: C1.1 C3.1 C4.1 R2.2 U1.5 | length 15.6
  Top Layer w0.75: v1(48.768,112.014) 48.768,113.132 48.793,113.157 U1.5 ; v1(50.038,112.014) 50.292,112.268 R2.2 ; R2.2@51.941,111.945 52.319,111.945 53.931,110.332 54.131,110.332 54.356,110.107 54.356,109.907 54.581,109.682 54.681,109.682 54.838,109.525 C1.1
  Bottom Layer w0.75: v1(50.038,112.014) 51.689,113.665 C4.1
  other v1: 48.768,111.252 50.038,111.252
MCU_LED1: R37.1 U7.40 | length 46.4
  Top Layer w0.254: U7.40 55.479,96.267 55.488,96.276 55.488,96.896 55.88,97.288 v1(55.88,97.409) ; v1(87.884,71.755) R37.1@89.408,71.755
  Bottom Layer w0.254: v1(55.88,97.409) 59.641,97.409 77.705,79.345 80.294,79.345 v1(87.884,71.755)
MCU_LED2: R38.1 U7.41 | length 46.4
  Top Layer w0.254: U7.41 54.979,98.032 v1(54.991,98.044) ; v1(87.884,75.819) 88.002,75.819 88.256,75.565 R38.1@89.408,75.565
  Bottom Layer w0.254: v1(54.991,98.044) 59.724,98.044 77.381,80.387 83.316,80.387 v1(87.884,75.819)
MCU_LED3: R39.1 U7.42 | length 46.9
  Top Layer w0.254: v1(54.174,98.672) 54.174,97.078 54.479,96.773 U7.42 ; v1(85.979,81.534) 87.82,79.692 89.035,79.692 89.408,79.319 R39.1
  Bottom Layer w0.254: v1(54.174,98.672) 54.177,98.675 59.825,98.675 76.966,81.534 v1(85.979,81.534)
MCU_LED4: R40.1 U7.43 | length 47
  Top Layer w0.254: v1(53.467,98.933) 53.425,98.891 53.425,97.185 53.97,96.64 53.97,95.364 U7.43 ; v1(85.471,82.55) 89.281,82.55 R40.1
  Bottom Layer w0.254: v1(53.467,98.933) 53.944,99.41 60.09,99.41 76.95,82.55 v1(85.471,82.55)
MCU_RESET: B3.19 C27.2 R32.2 U7.7 | length 45.5
  Top Layer w0.254: B3.19 42.586,71.89 42.276,71.58 42.242,71.58 41.529,70.868 C27.2 43.489,69.596 44.887,70.993 R32.2 45.283,70.993 46.681,69.596 52.483,69.596 52.632,69.745 52.632,74.79 52.965,75.123 52.965,79.939 52.959,79.945 52.959,83.163 52.81,83.312 49.022,83.312 v1(47.498,84.836) ; v1(45.75,90.25) 45.797,90.297 46.25,90.297 46.508,90.555 U7.7
  Bottom Layer w0.254: v1(45.75,90.25) 45.72,90.22 45.72,86.614 v1(47.498,84.836)
NetC2_1: C2.1 R2.1 U2.5 | length 11
  Top Layer w0.35: R2.1 54.102,112.07 54.427,111.745 54.626,111.745 55.62,110.75 v1(58.75,110.75) ; U2.5 61.021,110.137 61.471,110.587 61.471,110.721 v1(61.5,110.75) 61.5,110.791 61.805,111.096 61.805,111.741 C2.1
  Bottom Layer w0.35: v1(58.75,110.75) v1(61.5,110.75)
NetC2_2: C2.2 C4.2 U2.6 U3.2 U3.3 | length 32.1
  Top Layer w0.35: C2.2@59.874,111.983 60.058,111.799 60.058,109.868 U2.6
  Top Layer w0.381: v1(55.5,114) 55.5,112.446 56.576,111.37 58.387,111.37 58.675,111.657 59.28,111.657 59.69,112.066 C2.2 ; v1(57.25,104.5) 58.357,103.393 U3.2 ; v1(58,104.5) 58.032,104.5 58.489,104.043 U3.3 ; C2.2@59.28,112.676 59.874,112.083 C2.2@59.874,111.983
  Bottom Layer w0.75: C4.2 54.229,116.021 55.25,115 v1(55.5,115) v1(56.5,114) 56.5,105.347 57.347,104.5 v1(58,104.5)
  other v1: 56.5,115
NetC11_1: C11.1 U5.28 | length 6.3
  Top Layer w0.254: C11.1 90.451,113.665 C11.1@90.551,113.665
  Top Layer w0.5: U5.28 C11.1
NetC12_1: C12.1 U6.6 | length 19
  Top Layer w0.381: C12.1 45.212,84.507 45.622,84.098 45.722,84.098 47.777,82.042 v1(51.054,82.042) ; v1(58.293,76.835) 58.317,76.859 60.797,76.859 U6.6
  Bottom Layer w0.381: v1(51.054,82.042) 53.086,82.042 v1(58.293,76.835)
NetIC1_3: IC1.3 R16.1 | length 2.9
  Top Layer w0.35: R16.1 69.446,113.411 69.446,110.809 IC1.3
NetIC2_3: IC2.3 R28.1 | length 3.1
  Top Layer w0.35: IC2.3 64.707,110.845 64.707,113.35 R28.1 ; R28.1@64.603,113.302 R28.1@64.603,113.5
NetL1_1: L1.1 R5.2 | length 5.2
  Top Layer w0.35: R5.2 54.102,114.752 55.349,116 58.371,116 L1.1
NetL1_2: L1.2 R1.2 U1.4 U1.8 | length 33.5
  Top Layer w0.35: U1.8 48.939,117.029 49.846,117.029 v4(50.368,117.551) 51.181,118.364 59.322,118.364 60.393,117.292 60.393,116.01 L1.2
  Top Layer w0.5: v1(38.71,111.633) R1.2 41.552,111.633 U1.4@43.076,113.157
  Top Layer w0.6: U1.4@43.076,113.157 U1.4
  Bottom Layer w0.5: v1(38.71,111.633) 44.45,111.633 v4(50.368,117.551)
NetL1_3: L1.3 R3.2 | length 9.9
  Top Layer w0.381: R3.2 54.102,117.038 54.411,117.348 55.176,117.348 55.413,117.585 v4(55.499,117.585)
  Bottom Layer w0.381: v4(55.499,117.585) 61.295,117.585 62.611,116.268 L1.3
NetL2_1: L2.1 R26.2 | length 4.1
  Top Layer w0.8: R26.2@41.91,76.607 42.698,75.819 L2.1
NetLED1_2: LED1.2 R11.2 | length 2.1
  Top Layer w0.254: LED1.2@75.819,98.933 LED1.2
  Top Layer w0.381: R11.2 LED1.2@75.819,98.933
NetLED2_1: LED2.1 R15.1 | length 1.8
  Top Layer w0.381: R15.1 LED2.1
NetLED2_2: LED2.2 Q3.3 | length 4.8
  Top Layer w0.381: LED2.2 71.755,69.322 72.215,68.863 72.215,68.688 72.449,68.453 Q3.3 Q3.3@72.517,68.56
NetLED3_2: LED3.2 R37.2 | length 3.1
  Top Layer w0.254: R37.2@91.694,71.755 94.615,71.755 LED3.2
NetLED4_2: LED4.2 R38.2 | length 3.1
  Top Layer w0.254: R38.2@91.694,75.565 94.657,75.565 LED4.2
NetLED5_2: LED5.2 R39.2 | length 3.1
  Top Layer w0.254: R39.2 94.7,79.121 LED5.2
NetLED6_2: LED6.2 R40.2 | length 3
  Top Layer w0.254: R40.2 LED6.2
NETLIGHT: R13.1 U5.41 | length 8.6
  Top Layer w0.254: R13.1 75.946,100.767 76.971,99.741 76.971,98.181 77.797,97.355 80.091,97.355 81.051,96.395 U5.41
NetLS1_2: LS1.2 Q5.3 | length 8.5
  Top Layer w0.381: Q5.3 80.792,70.632 LS1.2
NetP1_1: P1.1 R22.2 | length 2
  Top Layer w1.4: P1.1 85.588,113.548 R22.2
NetP2_1: P2.1 R23.1 R26.1 | length 5.9
  Top Layer w1.5: P2.1 45.595,79.109 R23.1
NetQ1_1: Q1.1 R9.2 R12.1 | length 12.8
  Top Layer w0.381: R9.2 64.079,82.169 64.389,81.86 64.389,75.946 64.831,75.504 Q1.1 68.53,75.407 70.261,75.407 R12.1
NetQ2_1: Q2.1 R13.2 R14.1 | length 4.6
  Top Layer w0.381: Q2.1 75.847,103.444 76.294,102.997 R14.1 77.851,101.544 78.232,101.163 R13.2
NetQ2_3: Q2.3 R11.1 | length 3.6
  Top Layer w0.381: Q2.3 73.172,101.763 73.716,101.219 R11.1
NetQ3_1: Q3.1 R17.2 R18.1 | length 5.5
  Top Layer w0.381: R17.2 R18.1 ; R18.1@68.001,69.668 R18.1 ; Q3.1 69.949,69.403 69.375,69.977 R18.1
NetQ4_1: Q4.1 R24.2 R25.1 | length 7.4
  Top Layer w0.254: R24.2 R24.2@74.056,96.886
  Top Layer w0.381: R25.1 73.716,93.091 72.517,94.29 72.517,95.829 73.716,97.028 R24.2 ; R24.2@74.056,96.886 Q4.1
NetQ5_1: Q5.1 R29.2 R30.1 | length 5.4
  Top Layer w0.381: Q5.1 75.753,73.307 76.701,74.255 76.701,74.95 77.13,75.379 77.668,75.379 77.978,75.688 R29.2 R30.1
NetR3_1: R3.1 U1.7 | length 3.5
  Top Layer w0.35: U1.7 50.871,115.697 51.816,116.642 R3.1
NetR4_2: R4.2 U1.2 | length 6.7
  Top Layer w0.35: R4.2 37.536,114.681 37.861,115.006 38.806,115.951 42.696,115.951 42.775,115.872 43.201,115.872 U1.2
NetR5_1: R5.1 U1.6 | length 3
  Top Layer w0.35: U1.6 51.689,114.427 R5.1
NetR6_2: R6.2 U2.2 | length 5.2
  Top Layer w0.381: R6.2 57.531,106.807 57.531,107.346 57.838,107.653 58.893,107.653 59.254,108.013 60.678,108.013 60.96,107.731 60.96,107.696 60.986,107.67 60.986,107.085 U2.2
NetR7_1: R7.1 SIM1.6 | length 3.3
  Bottom Layer w0.254: SIM1.6 R7.1
NetR8_1: R8.1 SIM1.5 | length 30.2
  Bottom Layer w0.381: R8.1 89.281,72.089 91.393,69.977 SIM1.5
NetR9_1: R9.1 U7.32 | length 11.5
  Top Layer w0.254: U7.32 60.21,91.555 60.737,91.028 61.479,91.028 62.072,90.435 62.072,87.608 62.812,86.868 v1(64.135,86.868) ; v1(64.135,84.455) R9.1@64.262,84.455
  Bottom Layer w0.254: v1(64.135,84.455) v1(64.135,86.868)
NetR10_1: R10.1 SIM1.4 | length 3.4
  Bottom Layer w0.254: SIM1.4 93.916,97.853 R10.1
NetR19_2: R19.2 R20.2 U5.2 | length 7.9
  Top Layer w0.254: R19.2 83.439,85.796 83.812,86.169 84.32,86.169 R20.2@86.035,87.884 ; U5.2 85.601,88.317 R20.2@86.035,87.884 ; R20.2 R20.2@86.035,87.884
NetR20_1: R20.1 U7.12 | length 43.1
  Top Layer w0.254: U7.12 50.591,88.055 50.6,88.064 50.846,88.064 51.047,88.265 56.762,88.265 57.51,87.517 57.51,86.889 58.77,85.629 72.421,85.629 v1(73.694,86.902) ; R20.1@86.035,85.598 R20.1 86.233,83.687 86.487,83.433 v1(86.487,83.312) v1@86.536,83.361
  Bottom Layer w0.254: v1(73.694,86.902) 73.694,86.834 77.216,83.312 v1(86.487,83.312)
NetR21_1: R21.1 U7.13 | length 38.2
  Top Layer w0.254: v1(51.054,84.116) 51.054,84.237 51.479,84.662 U7.13 ; v1(59.086,86.899) 62.063,86.899 62.824,86.137 71.786,86.137 v1(73.66,88.011) ; v1(77.724,88.011) R21.1
  Bottom Layer w0.254: v1(51.054,84.116) 51.054,88.011 51.362,88.319 57.604,88.319 59.024,86.899 v1(59.086,86.899) ; v1(73.66,88.011) v1(77.724,88.011)
NetR21_2: R21.2 U5.1 | length 4.1
  Top Layer w0.381: R21.2 83.566,88.209 84.501,89.145 U5.1
NetR22_1: R22.1 U5.32 | length 3.6
  Top Layer w0.8: R22.1 85.6,111.25 85.6,107.646 U5.32
NetR24_1: R24.1 U7.29 | length 18.2
  Top Layer w0.254: U7.29 60.623,90.055 60.754,90.186 61.334,90.186 v1(61.381,90.233) ; v1(65.75,90.25) 71.327,90.25 71.628,90.551 v1(71.628,91.821)
  Bottom Layer w0.254: v1(61.381,90.233) 61.389,90.242 65.742,90.242 v1(65.75,90.25) ; v1(71.628,91.821) 73.914,94.107 v1(73.914,94.742)
NetU2_1: U2.1 U3.4 | length 3.1
  Top Layer w0.381: U2.1 60.071,105.002 60.38,104.693 U3.4
NetU2_3: U2.3 U3.5 | length 11
  Top Layer w0.381: U3.5 56.236,104.693 56.459,104.916 56.459,107.64 57.11,108.291 57.845,108.291 58.203,108.648 60.941,108.648 61.952,107.638 61.952,107.085 U2.3
NetU3_1: U3.1 U3.8 | length 5.8
  Top Layer w0.381: U3.8 U3.1
NetU4_2: U4.2 U7.31 | length 20
  Top Layer w0.254: U4.2 44.831,100.076 53.852,91.055 U7.31
NetU4_3: U4.3 U7.30 | length 20.3
  Top Layer w0.254: v1(46.101,100.965) U4.3 ; v1(53.209,90.555) U7.30
  Bottom Layer w0.254: v1(46.101,100.965) 46.101,98.806 53.209,91.698 v1(53.209,90.555)
NetU5_42: U5.42 U7.33 | length 25.1
  Top Layer w0.254: U7.33 60.623,92.055 60.678,92 v1(61.75,92) ; v1(64.178,91.864) 64.262,91.948 70.034,91.948 70.612,92.526 v1(70.612,92.583) ; v1(79.756,94.996) 79.825,94.996 80.124,95.295 U5.42
  Bottom Layer w0.254: v1(61.75,92) 62.751,92 62.88,91.871 64.172,91.871 v1(64.178,91.864) ; v1(70.612,92.583) 73.914,95.885 75.917,95.885 76.806,94.996 v1(79.756,94.996)
NetU6_2: U6.2 U7.22 | length 17.7
  Top Layer w0.254: U7.22 55.979,74.735 v1(56.038,74.676) ; v1(58.547,72.644) 58.616,72.644 58.741,72.519 U6.2
  Bottom Layer w0.254: v1(56.038,74.676) 56.089,74.676 56.724,74.041 57.726,74.041 58.462,73.306 58.462,72.729 v1(58.547,72.644)
NetU6_3: U6.3 U7.21 | length 18.7
  Top Layer w0.254: v1(55.468,73.406) 55.468,73.473 55.321,73.619 55.321,83.896 55.479,84.054 U7.21 ; v1(57.486,73.136) 57.553,73.136 58.036,73.619 U6.3
  Bottom Layer w0.254: v1(55.468,73.406) 57.095,73.406 57.365,73.136 v1(57.486,73.136)
OSC_IN: C18.2 U7.5 Y1.2 | length 15
  Top Layer w0.254: C18.2 39.156,94.488 40.513,95.845 40.513,96.139 41.275,96.901 Y1.2 42.037,96.901 47.383,91.555 U7.5
OSC_OUT: C20.2 U7.6 Y1.1 | length 12.5
  Top Layer w0.254: C20.2 40.894,91.821 Y1.1 42.418,91.821 45.395,91.821 46.161,91.055 U7.6
PWRKEY: B2.19 C17.2 Q4.3 U5.39 | length 17.6
  Top Layer w0.254: B2.19 77.343,86.487 76.708,87.122 76.708,91.418 77.427,92.137 78.14,92.137 78.613,92.61 C17.2 78.613,95.763 Q4.3 78.616,95.936 79.273,96.593 79.81,96.593 v1(79.883,96.52) ; v1(79.756,98.298) 79.825,98.298 80.122,98.595 U5.39
  Bottom Layer w0.254: v1(79.756,98.298) 79.819,98.234 79.819,96.584 v1(79.883,96.52)
RF_IN: R23.2 U6.11 | length 3.3
  Top Layer w0.8: R23.2 50.655,79.121 50.657,79.119 U6.11
SIM_CLK: R7.2 U5.16 | length 9.3
  Top Layer w0.254: v1(91.44,99.314) 92.159,98.595 U5.16
  Bottom Layer w0.254: v1(91.44,99.314) R7.2
SIM_DATA: C9.2 R8.2 U5.15 | length 14.3
  Top Layer w0.254: v1(96.685,97.752) 96.754,97.752 97.011,97.495 U5.15
  Bottom Layer w0.254: R8.2 89.479,100.33 89.852,100.703 89.852,100.722 91.238,102.108 C9.2 91.438,102.108 93.027,100.519 93.027,99.149 93.176,99 96.536,99 96.685,98.851 v1(96.685,97.752)
SIM_RST: R10.2 U5.17 | length 5.6
  Top Layer w0.254: v1(95.885,100.33) 96.52,99.695 U5.17
  Bottom Layer w0.254: R10.2 v1(95.885,100.33)
SIM_VDD: C8.1 SIM1.2 U5.18 | length 14.1
  Top Layer w0.25: v1(97.155,102.108) 97.204,102.059 97.587,102.059 ; U5.18@98.851,100.795 U5.18
  Top Layer w0.254: 97.587,102.059 U5.18@98.851,100.795
  Bottom Layer w0.254: C8.1 v1(97.155,102.108) 97.155,102.039 97.663,101.531 97.663,97.247 96.393,95.977 SIM1.2
SWCLK: H1.1 U7.37 | length 5
  Top Layer w0.254: H1.1 56.979,100.247 U7.37
SWDIO: H1.2 U7.34 | length 13.3
  Top Layer w0.254: v1(58.166,96.266) H1.2 ; U7.34 60.947,92.555 61.365,92.973 61.969,92.973 v1(61.996,93)
  Bottom Layer w0.254: v1(58.166,96.266) 59.88,96.266 61.996,94.151 v1(61.996,93)
TIMEPLUSE: R17.1 U6.4 | length 9.9
  Top Layer w0.381: U6.4 62.441,74.719 63.175,73.985 63.175,69.595 65.08,67.691 R17.1
VCC_RF: L2.2 U6.14 | length 3.2
  Top Layer w0.8: L2.2 U6.14
VDDA: C25.2 C26.2 R27.1 U7.9 | length 13.5
  Top Layer w0.254: C26.2 40.386,87.274 C25.2 40.715,87.503 42.418,89.206 42.418,89.734 42.728,90.043 43.124,90.043 43.613,89.555 U7.9
pads on no net: C1.s IC1.4 IC2.4 J1.4 SIM1.3 U1.GND U2.4 U4.7 U4.8 U4.9 U4.10 U4.11 U4.12 U4.13 U4.14 U4.15 U5.3 U5.4 U5.5 U5.6 U5.7 U5.9 U5.10 U5.11 U5.12 U5.14 U5.20 U5.22 U5.23 U5.24 U5.25 U5.26 U5.29 U5.38 U5.40 U6.5 U6.7 U6.13 U6.15 U6.16 U6.17 U6.18 U7.1 U7.2 U7.3 U7.4 U7.11 U7.14 U7.15 U7.16 U7.17 U7.18 U7.25 U7.26 U7.27 U7.38 U7.39 U7.45 U7.46

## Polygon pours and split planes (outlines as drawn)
GND on Bottom Layer "GND_L02_P017" (solid, pour order 17): 35,119.75 102.75,119.75 102.75,62.75 35,62.75
LIPO_CHARGER on Bottom Layer "LIPO_CHARGER_L02_P011" (solid, pour order 11): 48.25,111.25 ccw(c48.5,111.25) 48.5,111 50.25,111 ccw(c50.25,111.25) 50.5,111.25 50.5,112.25 ccw(c50.25,112.25) 50.25,112.5 48.5,112.5 ccw(c48.5,112.25) 48.25,112.25
NetC2_2 on Bottom Layer "NETC2_2_L02_P006" (solid, pour order 6): 56.5,115.5 cw(c56.5,114.896) 56.927,115.323 57.073,115.177 cw(c56.646,114.75) 57.25,114.75 57.25,114 cw(c56.646,114) 57.073,113.573 56.927,113.427 cw(c56.5,113.854) 56.5,113.25 55.5,113.25 cw(c55.5,113.854) 55.073,113.427 55,113.5 cw(c55.604,114.104) 54.75,114.104 54.75,115 55.25,115.5
LIPO_BATTERY on Bottom Layer "LIPO_BATTERY_L02_P000" (solid, pour order 0): 67.31,109.728 68.58,109.728 cw(c68.58,109.421) 68.797,109.638 68.961,109.474 68.961,108.077 cw(c68.654,108.077) 68.871,107.86 68.834,107.823 67.31,107.823 cw(c67.31,108.13) 67.093,107.913 67.056,107.95 67.056,109.601 67.093,109.638 cw(c67.31,109.421)
GND on Top Layer "GND_L01_P016" (solid, pour order 16): 35.052,119.634 35.052,62.865 102.743,62.865 102.743,119.634
NetC2_2 on Top Layer "NETC2_2_L01_P008" (solid, pour order 8): 56.5,115.5 cw(c56.5,114.896) 56.927,115.323 57.073,115.177 cw(c56.646,114.75) 57.25,114.75 57.25,114.104 cw(c56.396,114.104) 57,113.5 cw(c56.396,114.104) 56.396,113.25 55.604,113.25 cw(c55.604,114.104) 55,113.5 cw(c55.604,114.104) 54.75,114.104 54.75,114.5 cw(c55.957,114.5) 55.104,115.354 55.25,115.5
LIPO_BATTERY on Top Layer "LIPO_BATTERY_L01_P013" (solid, pour order 13): 67,109.25 cw(c67.5,109.25) 67.5,109.75 68.75,109.75 cw(c68.75,109.5) 69,109.5 69,108 cw(c68.75,108) 68.75,107.75 67.25,107.75 cw(c67.25,108) 67,108
LIPO_CHARGER on Top Layer "LIPO_CHARGER_L01_P001" (solid, pour order 1): 48.537,112.269 ccw(c48.54,111.898) 48.26,112.141 48.26,111.125 48.297,111.088 ccw(c48.514,111.305) 48.514,110.998 50.292,110.998 ccw(c50.292,111.305) 50.509,111.088 50.546,111.125 50.546,112.141 ccw(c50.266,111.898) 50.266,112.269

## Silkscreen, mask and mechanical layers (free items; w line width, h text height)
Bottom Overlay:
  text "+" at 51.333,115.291 h1
Mechanical 13:
  the board outline again, w0.254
